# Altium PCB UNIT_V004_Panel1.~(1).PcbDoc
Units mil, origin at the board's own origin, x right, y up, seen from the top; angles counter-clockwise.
Board outline 6145 x 6960 mil, 4 copper layers (Top Copper Layer, Internal Copper Layer 1, Internal Copper Layer 2, Bottom Copper Layer), stack 62.205 mil thick; 0 components, 0 nets, 93 pads, 0 vias.
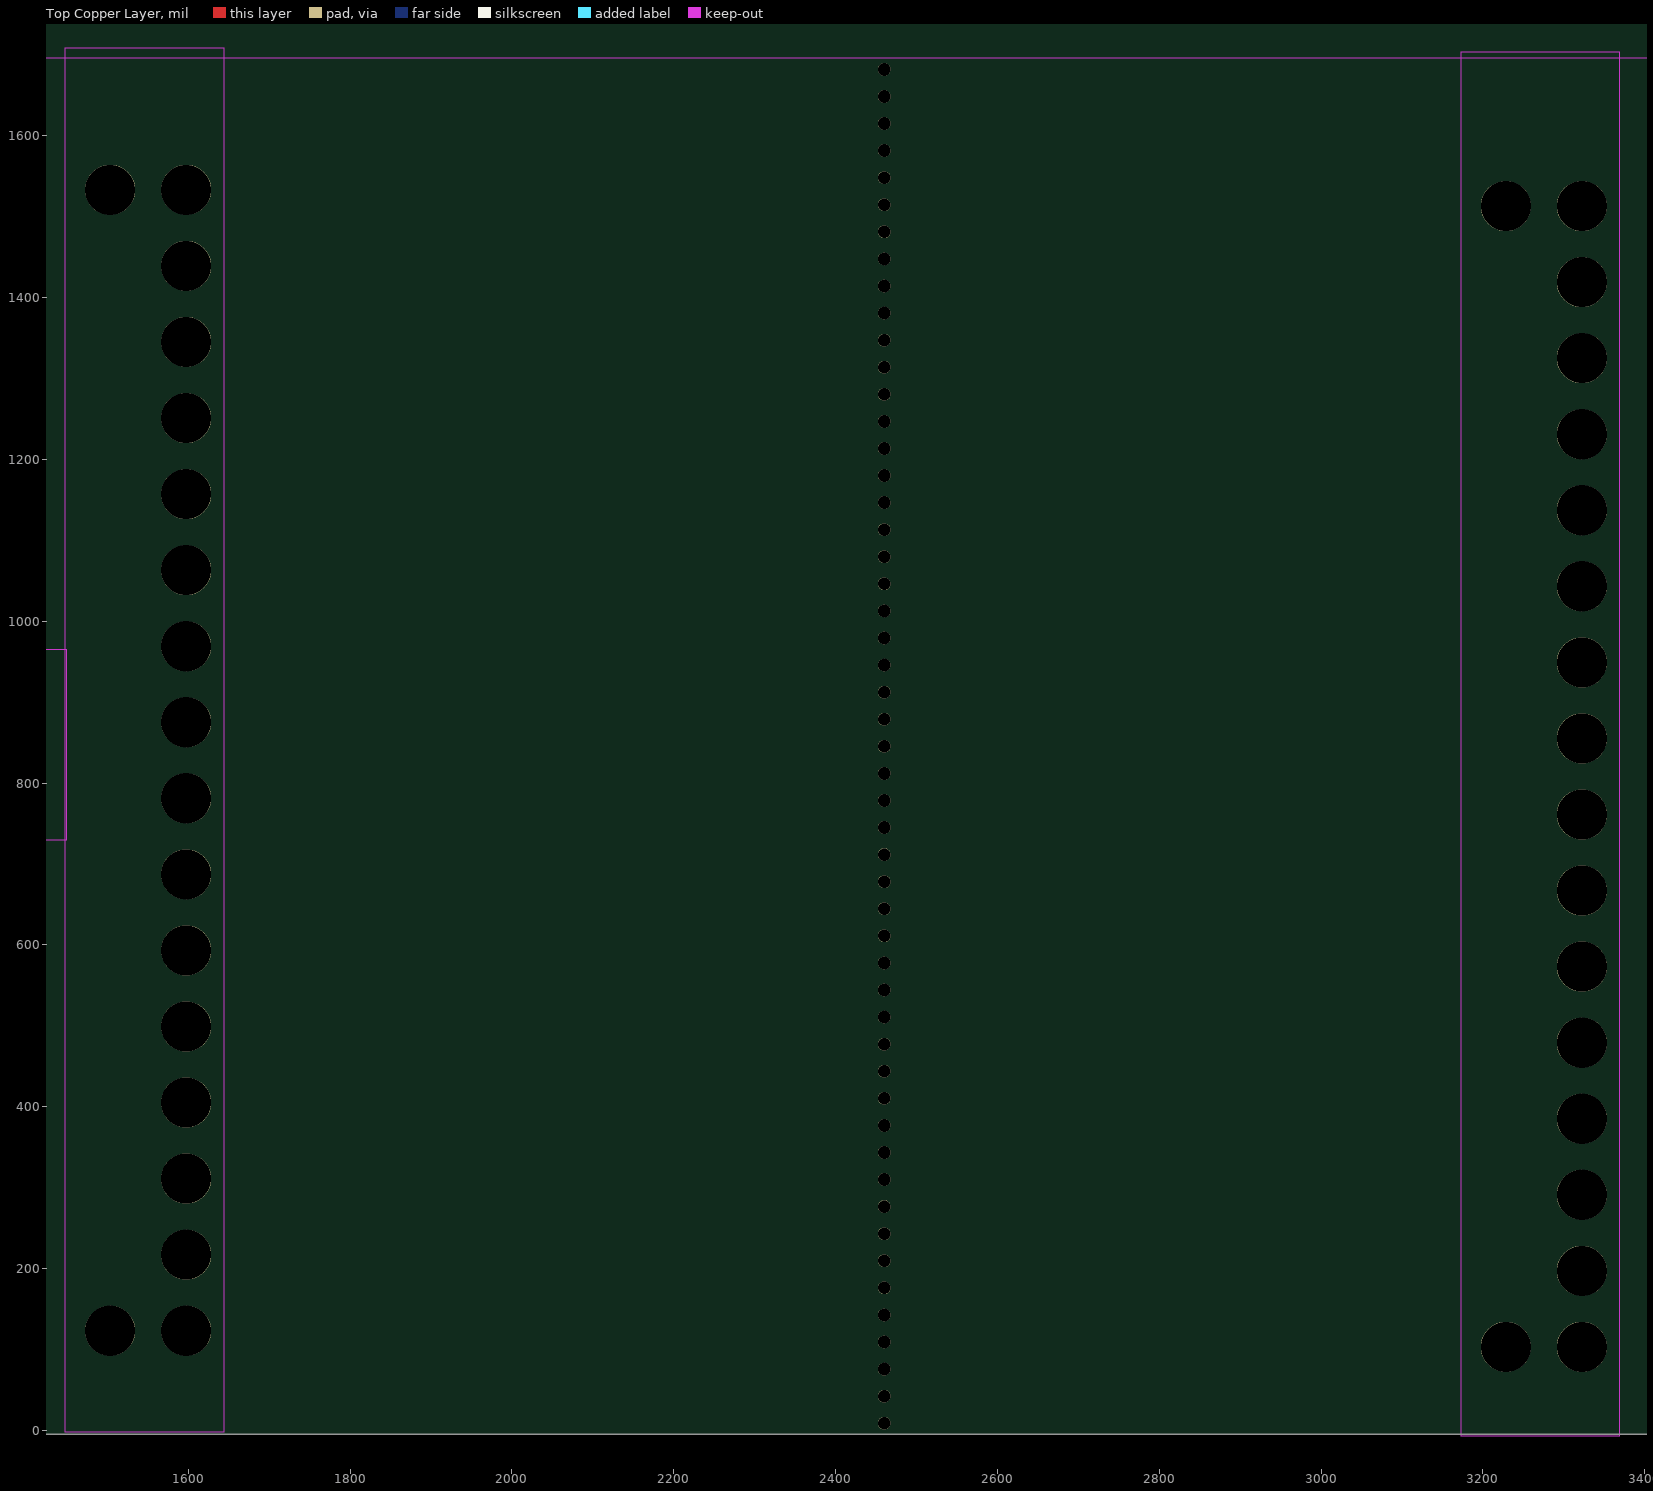
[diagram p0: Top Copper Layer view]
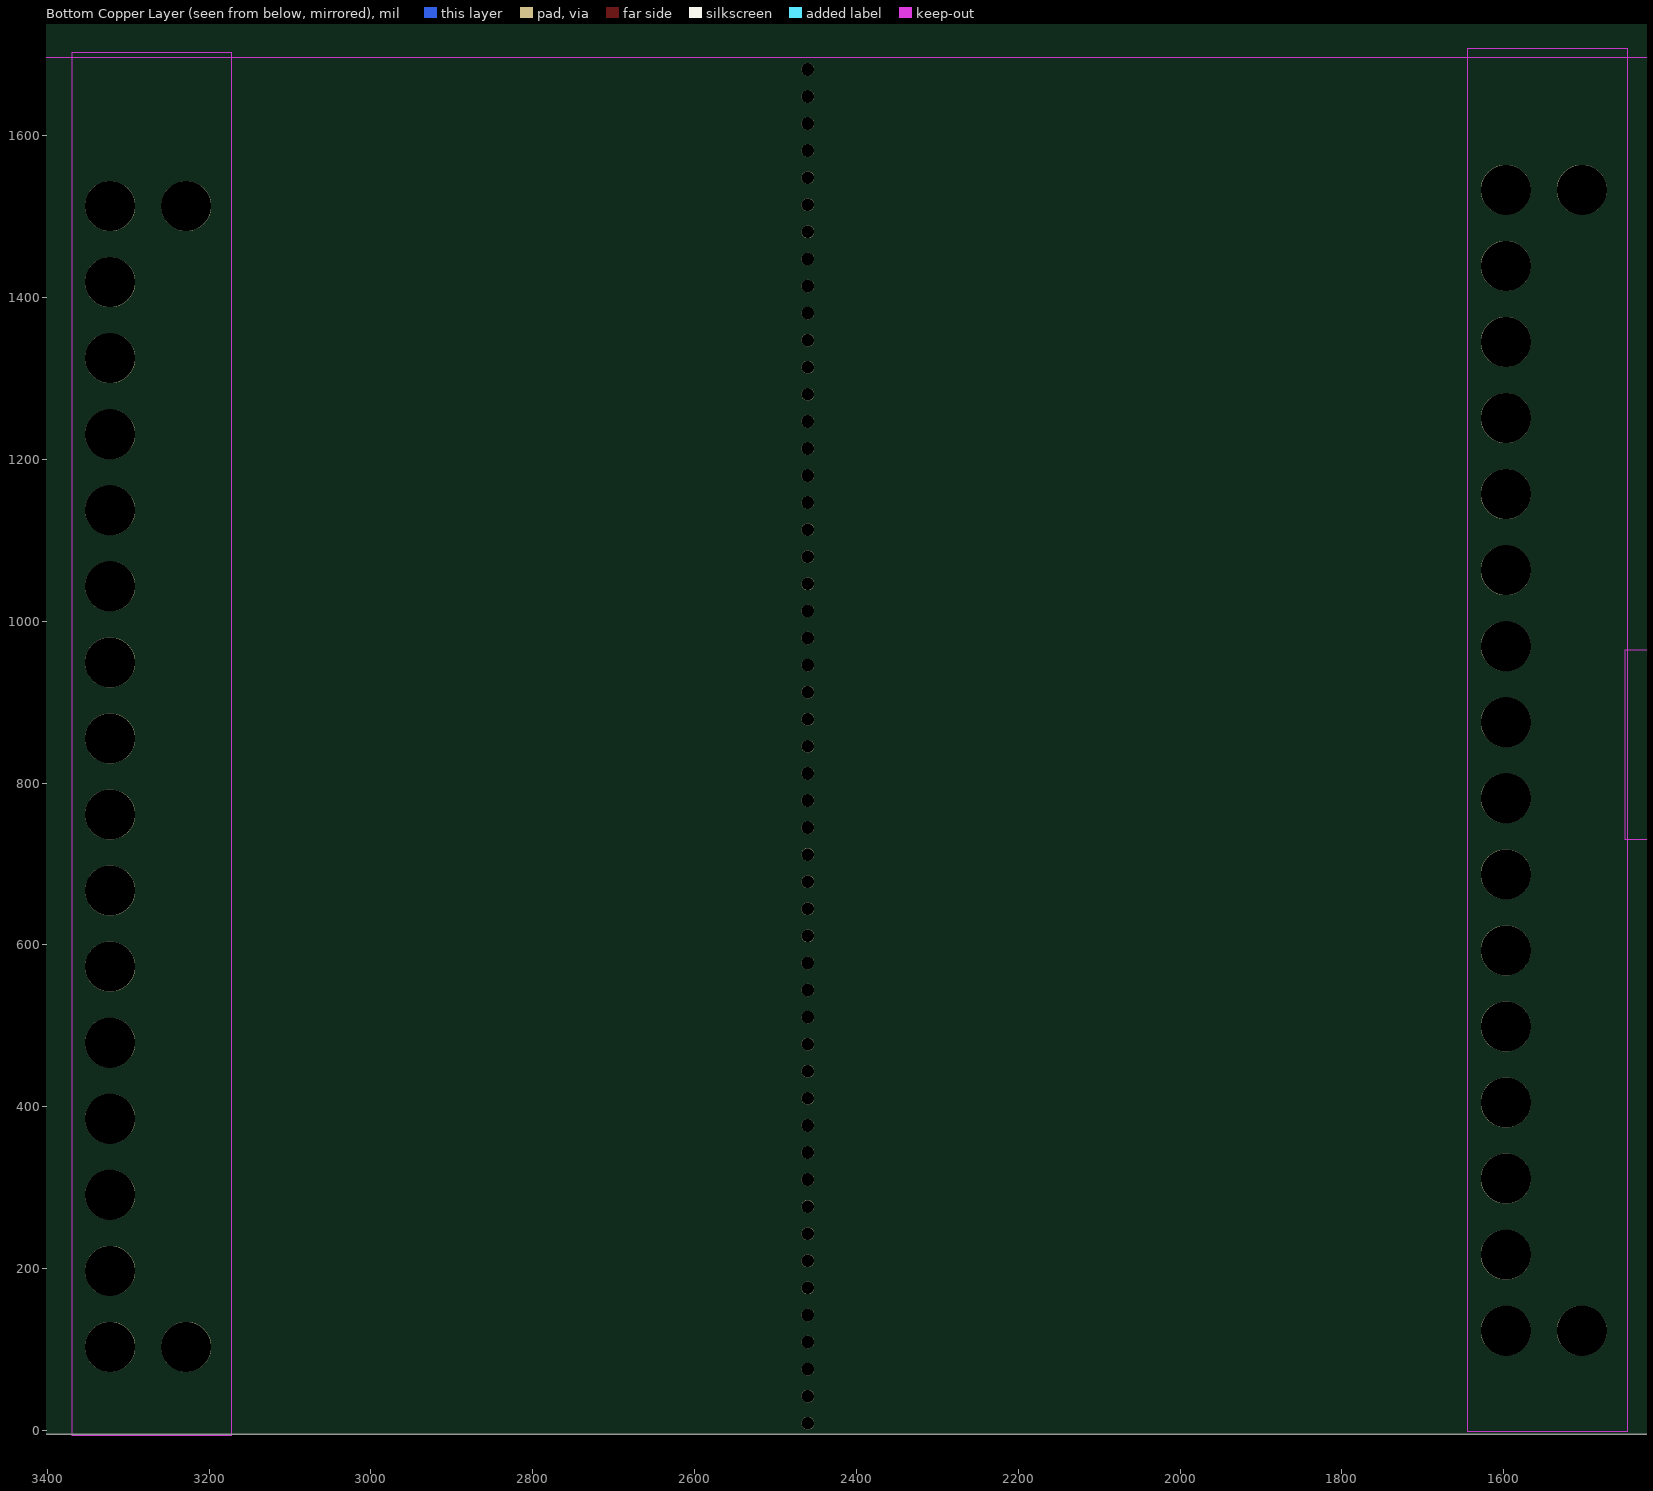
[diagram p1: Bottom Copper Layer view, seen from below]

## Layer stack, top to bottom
Top Solder: solder mask 0.3937, Solder Resist, Dk 3.5
Top Copper Layer: signal copper 1.378
Dielectric 1: prepreg 8.6614, FR-4, Dk 4.2
Internal Copper Layer 1: signal copper 1.378
Dielectric 2: core 39.3701, FR-4, Dk 4.2
Internal Copper Layer 2: signal copper 1.378
Dielectric 3: prepreg 8.6614, FR-4, Dk 4.2
Bottom Copper Layer: signal copper 1.378
Bottom Solder: solder mask 0.3937, Solder Resist, Dk 3.5

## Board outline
5,-5 6150,-5 6150,6955 5,6955

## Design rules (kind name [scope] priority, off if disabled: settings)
BoardOutlineClearance [All] p1: gap=9.84 ignorepadtopadclearanceinfootprint=FALSE
Clearance [All] p1: gap=4 ignorepadtopadclearanceinfootprint=FALSE
ComponentClearance [All] p1: gap=3.94 collisioncheckmode=3 verticalgap=3.94 showdistances=FALSE
HoleSize [All] p1: absolutevalues=TRUE maxlimit=100 minlimit=3.94 maxpercent=80.000 minpercent=20.000
HoleToHoleClearance [All] p1: gap=10.83 allowstackedmicrovias=TRUE
MinimumAnnularRing [All] p1: minimumring=3.94
MinimumSolderMaskSliver [All] p1: minsoldermaskwidth=2.95
PlaneClearance [All] p1: clearance=2.95
PlaneConnect [All] p1: planeconnectstyle=Relief reliefexpansion=5.91 reliefentries=4 reliefconductorwidth=2.95 reliefairgap=2.95
PolygonConnect [All] p1: connectstyle=Relief reliefconductorwidth=2.95 reliefentries=4 polygonreliefangle="90 Angle" airgapwidth=2.95
RoutingVias [All] p1: holewidth=9.84 width=23.62 viastyle="Through Hole" minholewidth=3.94 minwidth=7.87 maxholewidth=28 maxwidth=50
SilkToSilkClearance [All] p1: silktosilkclearance=5.91
SilkToSolderMaskClearance [IsPad] p1: minsilkscreentomaskgap=5.91 clearancetoexposedcopper=TRUE
SolderMaskExpansion [All] p1: expansion=2.95 istentingtop=FALSE
Width [All] p1: maxlimit=1968.5 minlimit=2.95 preferedwidth=5.91
22 further rules are at their usual default settings.

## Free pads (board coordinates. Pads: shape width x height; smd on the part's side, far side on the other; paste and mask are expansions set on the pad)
  round 15.75 hole 15.75 unplated: 15(2460,309.96) 15(2460,1246.97) 16(2460,276.5) 16(2460,1213.5) 17(2460,243.03) 17(2460,1180.04) 18(2460,8.78) 18(2460,209.57) 18(2460,1146.57) 19(2460,42.24) 19(2460,176.1) 19(2460,1113.11) 20(2460,75.71) 20(2460,142.64) 20(2460,745) 20(2460,1079.65) 20(2460,1682.01) 21(2460,109.17) 21(2460,109.17) 21(2460,711.54) 21(2460,1046.18) 21(2460,1648.54) 22(2460,678.07) 22(2460,1012.72) 22(2460,1615.08) 23(2460,644.61) 23(2460,979.25) 23(2460,1581.61) 24(2460,611.14) 24(2460,945.79) 24(2460,1548.15) 25(2460,577.68) 25(2460,912.32) 25(2460,1514.68) 26(2460,544.21) 26(2460,878.86) 26(2460,1481.22) 27(2460,510.75) 27(2460,845.39) 27(2460,1447.76) 28(2460,477.28) 28(2460,811.93) 28(2460,1414.29) 29(2460,443.82) 29(2460,778.46) 29(2460,1380.83) 30(2460,410.35) 30(2460,745) 30(2460,1347.36) 31(2460,343.43) 31(2460,1280.43) 32(2460,376.89) 32(2460,1313.9) 33(2460,410.35) 33(2460,410.35) 33(2460,1347.36) 33(2460,1347.36)
  round 62 hole 62: 27(1503.34,123.12) 27(3228.34,103.12) 28(1597.34,217.12) 28(3322.34,197.12) 36(1597.34,123.12) 36(3322.34,103.12) 37(1597.34,311.12) 37(3322.34,291.12) 38(1597.34,405.12) 38(3322.34,385.12) 45(1597.34,499.12) 45(3322.34,479.12) 46(1597.34,593.12) 46(3322.34,573.12) 47(1597.34,781.12) 47(3322.34,761.12) 48(1597.34,687.12) 48(3322.34,667.12) 55(1597.34,1157.12) 55(3322.34,1137.12) 56(1597.34,1063.12) 56(3322.34,1043.12) 57(1597.34,875.12) 57(3322.34,855.12) 58(1597.34,969.12) 58(3322.34,949.12) 66(1597.34,1533.12) 66(3322.34,1513.12) 67(1597.34,1345.12) 67(3322.34,1325.12) 68(1597.34,1251.12) 68(3322.34,1231.12) 77(1503.34,1533.12) 77(3228.34,1513.12) 78(1597.34,1439.12) 78(3322.34,1419.12)

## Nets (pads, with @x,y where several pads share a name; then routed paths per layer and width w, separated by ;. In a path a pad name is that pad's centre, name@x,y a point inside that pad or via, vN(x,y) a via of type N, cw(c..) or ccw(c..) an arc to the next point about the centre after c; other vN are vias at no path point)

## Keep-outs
Keep-Out Layer:
  rectangle: 1447.34,-1.88 1644.19,1708.12
  region: 6147.34,1696.27 6147.34,1893.12 5,1893.12 5,1696.27
  rectangle: 3172.34,-6.88 3369.19,1703.12
  rectangle: 630,-5 826.85,1700
  region: 1450,730 1450,965 5,965 5,730

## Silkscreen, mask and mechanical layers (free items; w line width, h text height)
Top Overlay:
  text "." at 927.04,1161.66 h30
  text "." at 110,1160 h30
  text "." at 925,195 h30
  text "." at 103.95,192.99 h30
Top Courtyard:
  lines w5: 5,6955 5,-5 6147.36,-5 ; 7.64,6955 6150,6955 6150,-5

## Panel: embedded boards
"..\Module_AFE\Module_AFE_B.PcbDoc" at 1447.41,965.78, 1 rows x 1 columns, spacing 816.85 x 970.16, rotation 90
"..\Module_AFE\Module_AFE_A.PcbDoc" at 630.88,964.68, 1 rows x 1 columns, spacing 816.85 x 970.16, rotation 90
"..\Module_AFE\Module_AFE_C.PcbDoc" at 624.64,-4.5, 1 rows x 1 columns, spacing 816.85 x 970.16, rotation 90
"..\MCS_adapter\MCS_adapter.PcbDoc" at 3372.34,-3.17, 1 rows x 1 columns, spacing 2500 x 1500, rotation 0
"..\Adapter_UNIT_SPI_TO_INTAN\Adapter_UNIT_SPI_TO_INTAN.PcbDoc" at 2472.34,1698.12, 1 rows x 1 columns, spacing 2500 x 1500, rotation 270
"..\Adapter_UNIT_SPI_TO_HDMI\Adapter_UNIT_SPI_TO_HDMI.PcbDoc" at 2487.66,-3.12, 1 rows x 1 columns, spacing 2500 x 1500, rotation 90
"..\Motherboard\Motherboard.PcbDoc" at 6.02,6954.75, 1 rows x 1 columns, spacing 2500 x 1500, rotation 270
"..\Module_AFE\Module_AFE_D.PcbDoc" at 1445.33,-1.98, 1 rows x 1 columns, spacing 816.85 x 970.16, rotation 90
